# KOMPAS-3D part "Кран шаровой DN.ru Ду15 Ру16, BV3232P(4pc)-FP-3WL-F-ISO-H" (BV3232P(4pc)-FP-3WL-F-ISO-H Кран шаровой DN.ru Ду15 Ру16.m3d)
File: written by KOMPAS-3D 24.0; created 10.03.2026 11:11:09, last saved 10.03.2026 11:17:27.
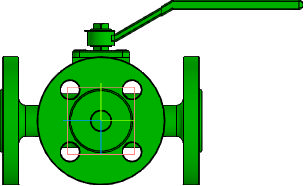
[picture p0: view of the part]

Document properties: Автор: R2D2; Полное имя файла: BV3232P(4pc)-FP-3WL-F-ISO-H Кран шаровой DN.ru Ду15 Ру16.cdw

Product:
- Part/product: Кран шаровой DN.ru Ду15 Ру16  | designation BV3232P(4pc)-FP-3WL-F-ISO-H
    Масса: 3.5
    Раздел спецификации: Прочие изделия
    Форматы листов документа: A2
    Примечание: D160-36355

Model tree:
1. Операция без истории:1

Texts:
  BV3232P(4pc)-FP-3WL-F-ISO-H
